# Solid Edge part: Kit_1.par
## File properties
Sűrűség: 0,000 kg/m^3
Pontosság: 0,990
Author: bmolnar
Last saved by: bmolnar
Revision: 77
Username: bmolnar
Dokumentum tartalom típus: 0
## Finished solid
Body 1: solid body, 44 faces, 61 edges, 51 vertices.
  Faces by surface: cylinder 15, cone 13, plane 12, torus 4
  Edges by curve: circle 47, line 14
Bounding box of the edges (mm; curved faces can reach further): 68.000 x 67.800 x 6.000, from (-34, -32.35, 80.35) to (34, 35.45, 86.35).
Cylindrical faces by radius (mm): R1.5 x2, R3 x4, R8.27 x1, R8.85 x1, R9 x1, R10.16 x1, R10.25 x1, R23.5 x1, R29.65 x1, R32.35 x1, R34 x1
Conical faces (half-angle, radius in mm at the cone's reference point): 3 deg R10.205 x1, 7 deg R9.5925 x1, 14 deg R8.135 x1, 14 deg R8.4811 x1, 17 deg R8.135 x1, 23 deg R8.829 x1, 42.5 deg R8.1233 x1, 45 deg R9.1 x2, 45 deg R23 x1, 84 deg R8.4608 x1, 85 deg R9.9463 x1, 87 deg R8.1765 x1
Toroidal faces (ring radius, tube radius in mm): R8.8057 r0.2025 x1, R9.2522 r0.2925 x1, R9.96 r0.2 x1, R24.3 r0.8 x1
Planar faces by outward normal: +z 7, -z 3, oblique 2
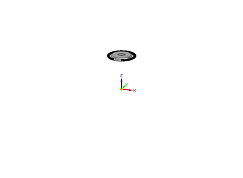
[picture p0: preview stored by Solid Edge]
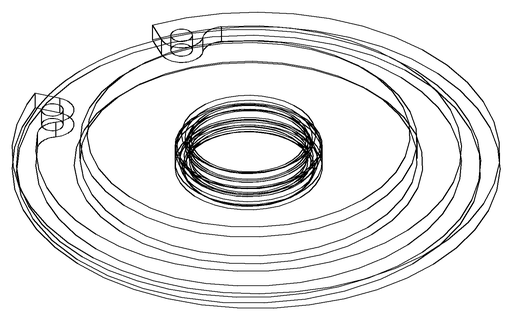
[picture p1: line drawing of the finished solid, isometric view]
